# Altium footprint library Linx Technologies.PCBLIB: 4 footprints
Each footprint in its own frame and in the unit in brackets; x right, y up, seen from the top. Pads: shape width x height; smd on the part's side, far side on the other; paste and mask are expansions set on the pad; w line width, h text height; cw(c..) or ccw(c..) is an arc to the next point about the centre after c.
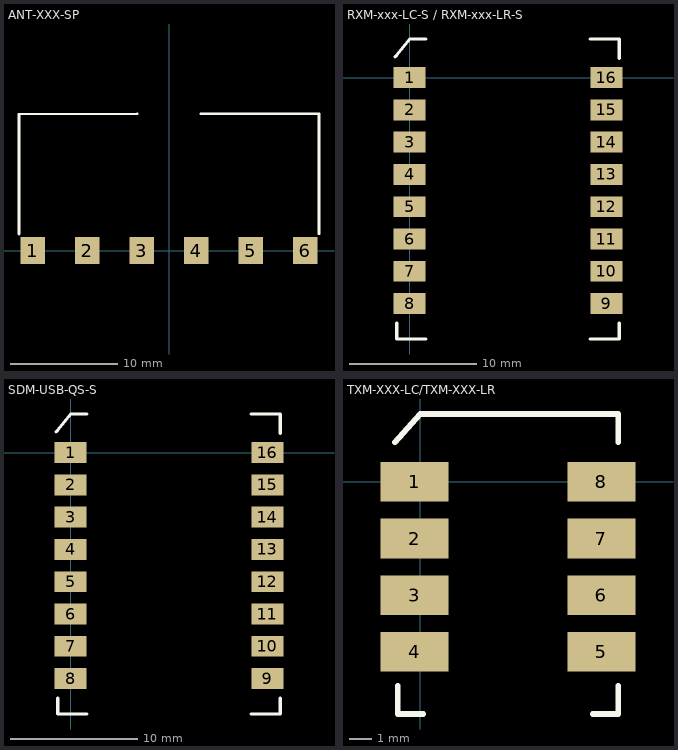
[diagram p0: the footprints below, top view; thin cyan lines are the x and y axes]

## ANT-XXX-SP [mil] "Linx Technologies Splatch Antenna"
height 62
pads (6):
  rect 90x100 smd: 1(-500,0) 2(-300,0) 3(-100,0) 4(100,0) 5(300,0) 6(500,0)
Top Overlay:
  lines w10: -551,61 -551,501 ; -548,501 -117.06,502 ; 117.06,502 548,502 ; 551,62 551,502

## RXM-xxx-LC-S / RXM-xxx-LR-S [mil] "Linx LC Series / LR series RF Receiver"
height 150
pads (16):
  rect 100x65 smd: 1(0,0) 2(0,-100) 3(0,-200) 4(0,-300) 5(0,-400) 6(0,-500) 7(0,-600) 8(0,-700) 9(610,-700) 10(610,-600) 11(610,-500) 12(610,-400) 13(610,-300) 14(610,-200) 15(610,-100) 16(610,0)
Top Overlay:
  lines w10: -45,65 -40,70 0,120 50,120 ; -40,-760 -40,-810 50,-810 ; 560,-810 650,-810 650,-760 ; 560,120 650,120 650,60

## SDM-USB-QS-S [mil] "Linx Technologies USB Transciever"
height 150
pads (16):
  rect 100x65 smd: 1(0,0) 2(0,-100) 3(0,-200) 4(0,-300) 5(0,-400) 6(0,-500) 7(0,-600) 8(0,-700) 9(610,-700) 10(610,-600) 11(610,-500) 12(610,-400) 13(610,-300) 14(610,-200) 15(610,-100) 16(610,0)
Top Overlay:
  lines w10: -45,65 -40,70 0,120 50,120 ; -40,-760 -40,-810 50,-810 ; 560,-810 650,-810 650,-760 ; 560,120 650,120 650,60

## TXM-XXX-LC/TXM-XXX-LR [mil] "LC series / LR series RF transmitter"
height 150
pads (8):
  rect 120x70 smd: 1(-10,0) 2(-10,-100) 3(-10,-200) 4(-10,-300) 5(320,-300) 6(320,-200) 7(320,-100) 8(320,0)
Top Overlay:
  lines w10: -45,70 0,120 350,120 350,70 ; -40,-360 -40,-410 5,-410 ; 305,-410 350,-410 350,-360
